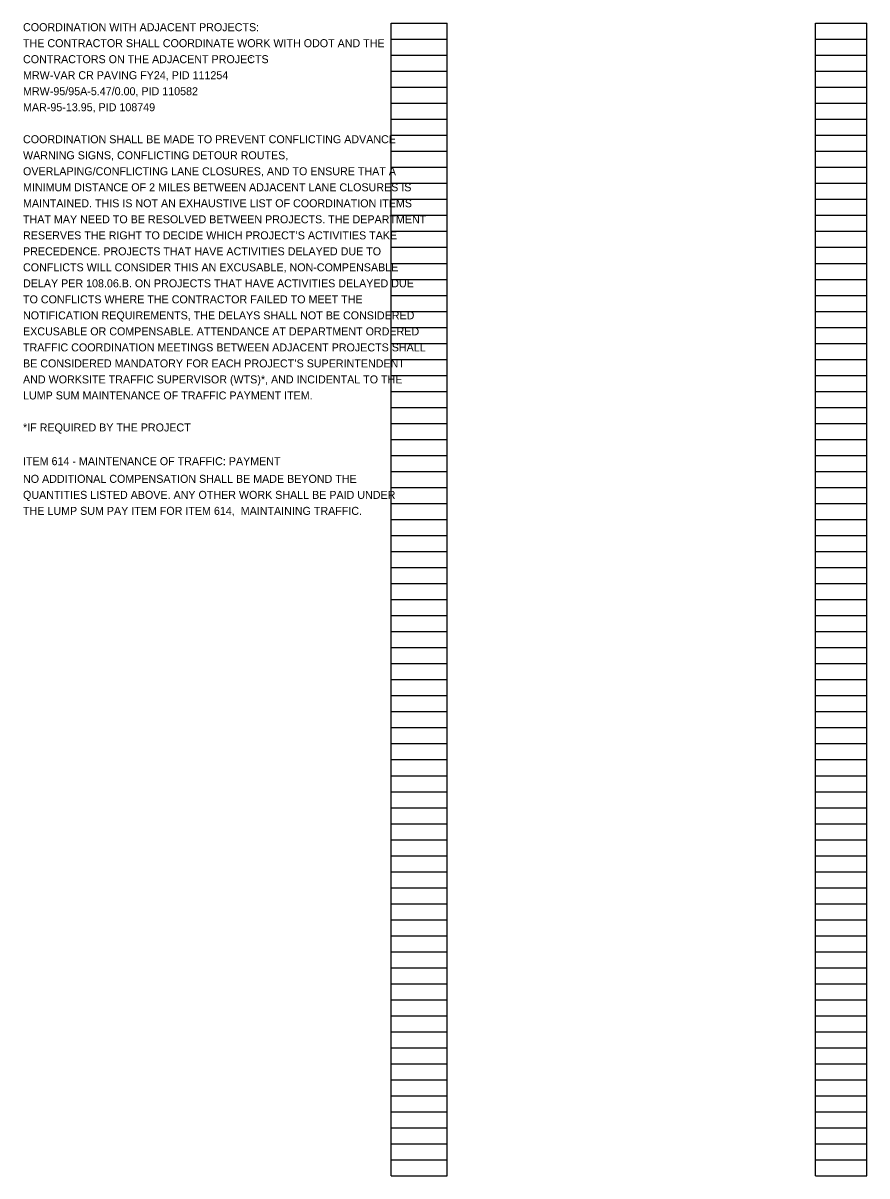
# Model space of a CAD drawing. Extents: x -23 to 32, y -58.1 to 21.1.
# Drawn here: x 17.24 to 32, y -57.17 to -37 of the extents above; entities that cross this region are included whole.
import ezdxf

# ---------------------------------------------------------------- set-up
doc = ezdxf.new("R2010")
doc.units = 0
doc.layers.add('SH_Data', color=7, linetype='Continuous')
doc.layers.add('SH_Text', color=7, linetype='Continuous')

msp = doc.modelspace()

# ---------------------------------------------------------------- linework, layer by layer
at = {"layer": 'SH_Data'}
for p, q in [((23.68, -57.165), (23.68, -37.005)), ((23.68, -37.005), (24.66, -37.005)), ((24.66, -57.165), (24.66, -37.005)), ((31.1, -57.165), (31.1, -37.005)), ((31.1, -37.005), (32, -37.005)), ((32, -57.165), (32, -37.005)), ((23.68, -37.285), (24.66, -37.285)), ((31.1, -37.285), (32, -37.285)), ((23.68, -37.565), (24.66, -37.565)), ((31.1, -37.565), (32, -37.565)), ((23.68, -37.845), (24.66, -37.845)), ((31.1, -37.845), (32, -37.845)), ((23.68, -38.125), (24.66, -38.125)), ((31.1, -38.125), (32, -38.125)), ((23.68, -38.405), (24.66, -38.405)), ((31.1, -38.405), (32, -38.405)), ((23.68, -38.685), (24.66, -38.685)), ((31.1, -38.685), (32, -38.685)), ((23.68, -38.965), (24.66, -38.965)), ((31.1, -38.965), (32, -38.965)), ((23.68, -39.245), (24.66, -39.245)), ((31.1, -39.245), (32, -39.245)), ((23.68, -39.525), (24.66, -39.525)), ((31.1, -39.525), (32, -39.525)), ((23.68, -39.805), (24.66, -39.805)), ((31.1, -39.805), (32, -39.805)), ((23.68, -40.085), (24.66, -40.085)), ((31.1, -40.085), (32, -40.085)), ((23.68, -40.365), (24.66, -40.365)), ((31.1, -40.365), (32, -40.365)), ((23.68, -40.645), (24.66, -40.645)), ((31.1, -40.645), (32, -40.645)), ((23.68, -40.925), (24.66, -40.925)), ((31.1, -40.925), (32, -40.925)), ((23.68, -41.205), (24.66, -41.205)), ((31.1, -41.205), (32, -41.205)), ((23.68, -41.485), (24.66, -41.485)), ((31.1, -41.485), (32, -41.485)), ((23.68, -41.765), (24.66, -41.765)), ((31.1, -41.765), (32, -41.765)), ((23.68, -42.045), (24.66, -42.045)), ((31.1, -42.045), (32, -42.045)), ((23.68, -42.325), (24.66, -42.325)), ((31.1, -42.325), (32, -42.325)), ((23.68, -42.605), (24.66, -42.605)), ((31.1, -42.605), (32, -42.605)), ((23.68, -42.885), (24.66, -42.885)), ((31.1, -42.885), (32, -42.885)), ((23.68, -43.165), (24.66, -43.165)), ((31.1, -43.165), (32, -43.165)), ((23.68, -43.445), (24.66, -43.445)), ((31.1, -43.445), (32, -43.445)), ((23.68, -43.725), (24.66, -43.725)), ((31.1, -43.725), (32, -43.725)), ((23.68, -44.005), (24.66, -44.005)), ((31.1, -44.005), (32, -44.005)), ((23.68, -44.285), (24.66, -44.285)), ((31.1, -44.285), (32, -44.285)), ((23.68, -44.565), (24.66, -44.565)), ((31.1, -44.565), (32, -44.565)), ((23.68, -44.845), (24.66, -44.845)), ((31.1, -44.845), (32, -44.845)), ((23.68, -45.125), (24.66, -45.125)), ((31.1, -45.125), (32, -45.125)), ((23.68, -45.405), (24.66, -45.405)), ((31.1, -45.405), (32, -45.405)), ((23.68, -45.685), (24.66, -45.685)), ((31.1, -45.685), (32, -45.685)), ((23.68, -45.965), (24.66, -45.965)), ((31.1, -45.965), (32, -45.965)), ((23.68, -46.245), (24.66, -46.245)), ((31.1, -46.245), (32, -46.245)), ((23.68, -46.525), (24.66, -46.525)), ((31.1, -46.525), (32, -46.525)), ((23.68, -46.805), (24.66, -46.805)), ((31.1, -46.805), (32, -46.805)), ((23.68, -47.085), (24.66, -47.085)), ((31.1, -47.085), (32, -47.085)), ((23.68, -47.365), (24.66, -47.365)), ((31.1, -47.365), (32, -47.365)), ((23.68, -47.645), (24.66, -47.645)), ((31.1, -47.645), (32, -47.645)), ((23.68, -47.925), (24.66, -47.925)), ((31.1, -47.925), (32, -47.925)), ((23.68, -48.205), (24.66, -48.205)), ((31.1, -48.205), (32, -48.205)), ((23.68, -48.485), (24.66, -48.485)), ((31.1, -48.485), (32, -48.485)), ((23.68, -48.765), (24.66, -48.765)), ((31.1, -48.765), (32, -48.765)), ((23.68, -49.045), (24.66, -49.045)), ((31.1, -49.045), (32, -49.045)), ((23.68, -49.325), (24.66, -49.325)), ((31.1, -49.325), (32, -49.325)), ((23.68, -49.605), (24.66, -49.605)), ((31.1, -49.605), (32, -49.605)), ((23.68, -49.885), (24.66, -49.885)), ((31.1, -49.885), (32, -49.885)), ((23.68, -50.165), (24.66, -50.165)), ((31.1, -50.165), (32, -50.165)), ((23.68, -50.445), (24.66, -50.445)), ((31.1, -50.445), (32, -50.445)), ((23.68, -50.725), (24.66, -50.725)), ((31.1, -50.725), (32, -50.725)), ((23.68, -51.005), (24.66, -51.005)), ((31.1, -51.005), (32, -51.005)), ((23.68, -51.285), (24.66, -51.285)), ((31.1, -51.285), (32, -51.285)), ((23.68, -51.565), (24.66, -51.565)), ((31.1, -51.565), (32, -51.565)), ((23.68, -51.845), (24.66, -51.845)), ((31.1, -51.845), (32, -51.845)), ((23.68, -52.125), (24.66, -52.125)), ((31.1, -52.125), (32, -52.125)), ((23.68, -52.405), (24.66, -52.405)), ((31.1, -52.405), (32, -52.405)), ((23.68, -52.685), (24.66, -52.685)), ((31.1, -52.685), (32, -52.685)), ((23.68, -52.965), (24.66, -52.965)), ((31.1, -52.965), (32, -52.965)), ((23.68, -53.245), (24.66, -53.245)), ((31.1, -53.245), (32, -53.245)), ((23.68, -53.525), (24.66, -53.525)), ((31.1, -53.525), (32, -53.525)), ((23.68, -53.805), (24.66, -53.805)), ((31.1, -53.805), (32, -53.805)), ((23.68, -54.085), (24.66, -54.085)), ((31.1, -54.085), (32, -54.085)), ((23.68, -54.365), (24.66, -54.365)), ((31.1, -54.365), (32, -54.365)), ((23.68, -54.645), (24.66, -54.645)), ((31.1, -54.645), (32, -54.645)), ((23.68, -54.925), (24.66, -54.925)), ((31.1, -54.925), (32, -54.925)), ((23.68, -55.205), (24.66, -55.205)), ((31.1, -55.205), (32, -55.205)), ((23.68, -55.485), (24.66, -55.485)), ((31.1, -55.485), (32, -55.485)), ((23.68, -55.765), (24.66, -55.765)), ((31.1, -55.765), (32, -55.765)), ((23.68, -56.045), (24.66, -56.045)), ((31.1, -56.045), (32, -56.045)), ((23.68, -56.325), (24.66, -56.325)), ((31.1, -56.325), (32, -56.325)), ((23.68, -56.605), (24.66, -56.605)), ((31.1, -56.605), (32, -56.605)), ((23.68, -56.885), (24.66, -56.885)), ((31.1, -56.885), (32, -56.885)), ((23.68, -57.165), (24.66, -57.165)), ((31.1, -57.165), (32, -57.165))]:
    msp.add_line(p, q, dxfattribs=at)

# ---------------------------------------------------------------- texts
at = {"layer": 'SH_Text'}
for s, p in [('COORDINATION WITH ADJACENT PROJECTS:', (17.24, -37.145)), ('THE CONTRACTOR SHALL COORDINATE WORK WITH ODOT AND THE ', (17.24, -37.425)), ('CONTRACTORS ON THE ADJACENT PROJECTS', (17.24, -37.705)), (': ', (21.201, -37.705)), ('MRW-VAR CR PAVING FY24, PID 111254', (17.24, -37.985)), ('MRW-95/95A-5.47/0.00, PID 110582', (17.24, -38.265)), ('MAR-95-13.95, PID 108749', (17.24, -38.545)), ('COORDINATION SHALL BE MADE TO PREVENT CONFLICTING ADVANCE ', (17.24, -39.105)), ('WARNING SIGNS, CONFLICTING DETOUR ROUTES, ', (17.24, -39.385)), ('OVERLAPING/CONFLICTING LANE CLOSURES, AND TO ENSURE THAT A ', (17.24, -39.665)), ('MINIMUM DISTANCE OF 2 MILES BETWEEN ADJACENT LANE CLOSURES IS ', (17.24, -39.945)), ('MAINTAINED. THIS IS NOT AN EXHAUSTIVE LIST OF COORDINATION ITEMS ', (17.24, -40.225)), ('THAT MAY NEED TO BE RESOLVED BETWEEN PROJECTS. THE DEPARTMENT ', (17.24, -40.505)), ('RESERVES THE RIGHT TO DECIDE WHICH PROJECT’S ACTIVITIES TAKE ', (17.24, -40.785)), ('PRECEDENCE. PROJECTS THAT HAVE ACTIVITIES DELAYED DUE TO ', (17.24, -41.065)), ('CONFLICTS WILL CONSIDER THIS AN EXCUSABLE, NON-COMPENSABLE ', (17.24, -41.345)), ('DELAY PER 108.06.B. ON PROJECTS THAT HAVE ACTIVITIES DELAYED DUE ', (17.24, -41.625)), ('TO CONFLICTS WHERE THE CONTRACTOR FAILED TO MEET THE ', (17.24, -41.905)), ('NOTIFICATION REQUIREMENTS, THE DELAYS SHALL NOT BE CONSIDERED ', (17.24, -42.185)), ('EXCUSABLE OR COMPENSABLE. ATTENDANCE AT DEPARTMENT ORDERED ', (17.24, -42.465)), ('TRAFFIC COORDINATION MEETINGS BETWEEN ADJACENT PROJECTS SHALL ', (17.24, -42.745)), ('BE CONSIDERED MANDATORY FOR EACH PROJECT’S SUPERINTENDENT ', (17.24, -43.025)), ('AND WORKSITE TRAFFIC SUPERVISOR (WTS)*, AND INCIDENTAL TO THE ', (17.24, -43.305)), ('LUMP SUM MAINTENANCE OF TRAFFIC PAYMENT ITEM.', (17.24, -43.585)), ('*IF REQUIRED BY THE PROJECT', (17.24, -44.145)), ('ITEM 614 - MAINTENANCE OF TRAFFIC: PAYMENT', (17.24, -44.735)), ('NO ADDITIONAL COMPENSATION SHALL BE MADE BEYOND THE ', (17.24, -45.044)), ('QUANTITIES LISTED ABOVE. ANY OTHER WORK SHALL BE PAID UNDER ', (17.24, -45.324)), ('THE LUMP SUM PAY ITEM FOR ITEM 614,  MAINTAINING TRAFFIC.', (17.24, -45.604))]:
    msp.add_text(s, height=0.14, dxfattribs=at).set_placement(p)

doc.saveas('drawing.dxf')
